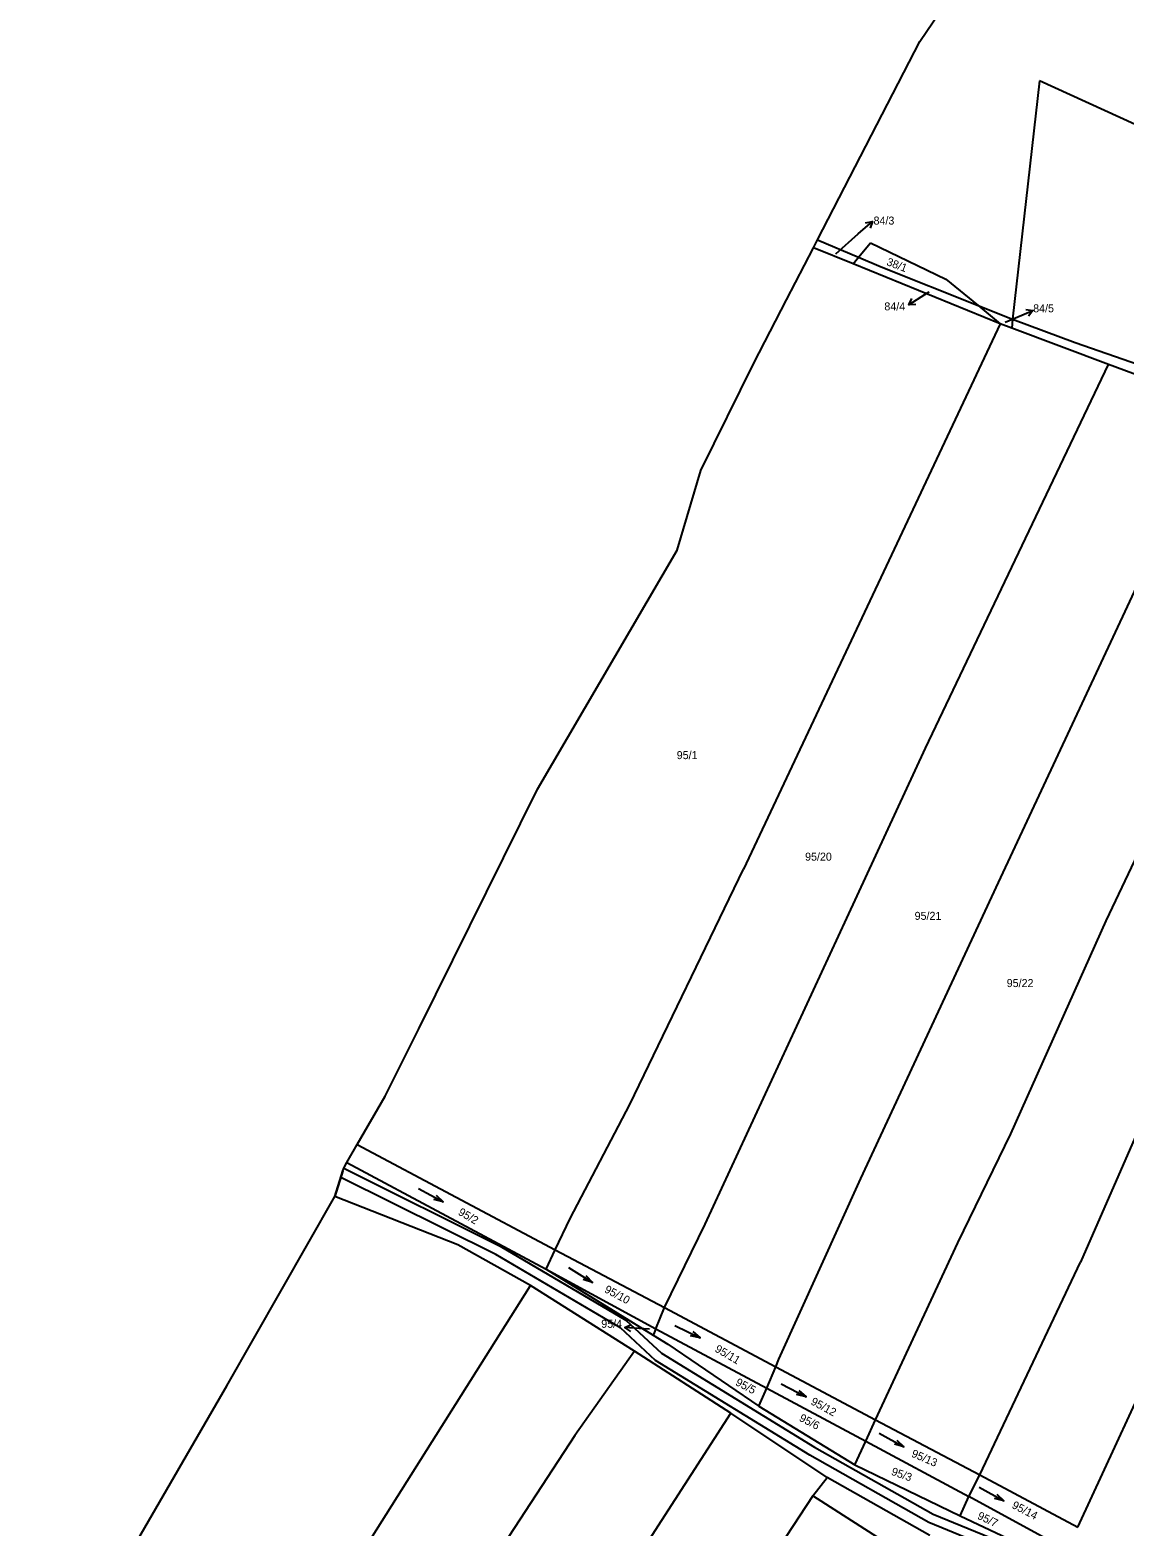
# Model space of a CAD drawing. Extents: x -747333 to -745433, y -1133152 to -1130600.
# Drawn here: x -746763 to -746530.4, y -1131462 to -1131144.2 of the extents above; entities that cross this region are included whole.
import ezdxf

# ---------------------------------------------------------------- set-up
doc = ezdxf.new("R2010")
doc.units = 0
for name, color, linetype in [('Vrstva 1', 7, 'Continuous'), ('Vrstva 13', 7, 'Continuous'), ('Vrstva 16', 7, 'Continuous'), ('Vrstva 18', 7, 'Continuous'), ('Vrstva 25', 7, 'Continuous'), ('Vrstva 30', 7, 'Continuous'), ('Vrstva 52', 7, 'Continuous'), ('Vrstva 6', 7, 'Continuous')]:
    doc.layers.add(name, color=color, linetype=linetype)

msp = doc.modelspace()

# ---------------------------------------------------------------- linework, layer by layer
at = {"layer": 'Vrstva 1'}
for points in [[(-746595.54, -1131188.72), (-746586.85, -1131192.45)], [(-746588, -1131193.84), (-746596.42, -1131190.42)], [(-746586.85, -1131192.45), (-746582.06, -1131194.51)], [(-746556.74, -1131206.56), (-746588, -1131193.84)], [(-746582.06, -1131194.51), (-746561.42, -1131202.72)], [(-746561.42, -1131202.72), (-746554.12, -1131205.63)], [(-746554.12, -1131205.63), (-746540.76, -1131210.57)], [(-746554.27, -1131207.49), (-746556.74, -1131206.56)], [(-746533.7, -1131215.25), (-746554.27, -1131207.49)], [(-746540.76, -1131210.57), (-746507.14, -1131222.24)], [(-746509.39, -1131224.25), (-746533.7, -1131215.25)], [(-746693.38, -1131380.95), (-746651.29, -1131403.28)], [(-746695.57, -1131384.74), (-746653.24, -1131407.37)], [(-746672.02, -1131402.26), (-746698.14, -1131392)], [(-746656.6, -1131410.85), (-746672.02, -1131402.26)], [(-746651.29, -1131403.28), (-746628.09, -1131415.58)], [(-746653.24, -1131407.37), (-746629.9, -1131420.11)], [(-746653.24, -1131407.37), (-746630.51, -1131421.39)], [(-746634.47, -1131424.8), (-746656.6, -1131410.85)], [(-746628.09, -1131415.58), (-746604.44, -1131428.12)], [(-746630.51, -1131421.39), (-746627.36, -1131423.33)], [(-746629.9, -1131420.11), (-746606.35, -1131432.7)], [(-746613.96, -1131437.96), (-746634.47, -1131424.8)], [(-746627.36, -1131423.33), (-746608.05, -1131436.52)], [(-746604.44, -1131428.12), (-746583.2, -1131439.38)], [(-746606.35, -1131432.7), (-746585.32, -1131443.94)], [(-746608.05, -1131436.52), (-746587.65, -1131448.97)], [(-746593.49, -1131451.66), (-746613.96, -1131437.96)], [(-746583.2, -1131439.38), (-746561.09, -1131451.11)], [(-746585.32, -1131443.94), (-746563.37, -1131455.67)], [(-746587.65, -1131448.97), (-746565.25, -1131459.83)], [(-746571.68, -1131464), (-746593.49, -1131451.66)], [(-746561.09, -1131451.11), (-746540.23, -1131462.22)], [(-746542.47, -1131467.06), (-746563.37, -1131455.67)], [(-746565.25, -1131459.83), (-746543.78, -1131469.9)]]:
    msp.add_lwpolyline(points, dxfattribs=at)
at = {"layer": 'Vrstva 13'}
for points in [[(-746573.83, -1131146.6), (-746562.93, -1131130.47)], [(-746595.54, -1131188.72), (-746573.83, -1131146.6)], [(-746596.42, -1131190.42), (-746595.54, -1131188.72)], [(-746602.14, -1131201.52), (-746596.42, -1131190.42)], [(-746609.07, -1131214.96), (-746602.14, -1131201.52)], [(-746620.38, -1131237.72), (-746609.07, -1131214.96)], [(-746625.38, -1131254.67), (-746620.38, -1131237.72)], [(-746655.09, -1131305.42), (-746625.38, -1131254.67)], [(-746680.29, -1131356.36), (-746655.09, -1131305.42)], [(-746687.43, -1131370.65), (-746680.29, -1131356.36)], [(-746693.38, -1131380.95), (-746687.43, -1131370.65)], [(-746695.57, -1131384.74), (-746693.38, -1131380.95)], [(-746696.44, -1131386.49), (-746698.14, -1131392)], [(-746696.44, -1131386.49), (-746696.27, -1131385.95)], [(-746696.27, -1131385.95), (-746695.57, -1131384.74)], [(-746721.13, -1131432.18), (-746698.14, -1131392)], [(-746762.97, -1131504.51), (-746721.13, -1131432.18)]]:
    msp.add_lwpolyline(points, dxfattribs=at)
at = {"layer": 'Vrstva 16'}
for p, q in [((-746585.374858, -1131185.149161), (-746583.90426, -1131184.849426)), ((-746574.676174, -1131202.512401), (-746576.175913, -1131202.569693)), ((-746551.281717, -1131203.574896), (-746549.793754, -1131203.771025)), ((-746635.255066, -1131420.633127), (-746636.500588, -1131419.795766))]:
    msp.add_line(p, q, dxfattribs=at)
for points in [[(-746586.9, -1131187.5), (-746583.90426, -1131184.849426), (-746584.380893, -1131186.272564)], [(-746591.68, -1131191.73), (-746586.9, -1131187.5)], [(-746572.79, -1131200.44), (-746576.175913, -1131202.569693), (-746575.474809, -1131201.242684)], [(-746571.88, -1131199.87), (-746572.79, -1131200.44)], [(-746555.7, -1131206.21), (-746553.49, -1131205.3)], [(-746553.49, -1131205.3), (-746549.793754, -1131203.771025), (-746550.708351, -1131204.960988)], [(-746632.51, -1131420.07), (-746636.500588, -1131419.795766), (-746635.152228, -1131419.136657)], [(-746631.28, -1131420.15), (-746632.51, -1131420.07)]]:
    msp.add_lwpolyline(points, dxfattribs=at)
at = {"layer": 'Vrstva 25'}
for p, q in [((-746680.399719, -1131390.263234), (-746675.100281, -1131393.076766)), ((-746648.472186, -1131407.017113), (-746643.387814, -1131410.202887)), ((-746625.883282, -1131419.33836), (-746620.516718, -1131422.02164)), ((-746603.316861, -1131431.736771), (-746598.003139, -1131434.523229)), ((-746582.42364, -1131442.235176), (-746577.17636, -1131445.144824)), ((-746561.217227, -1131453.721663), (-746555.962773, -1131456.618337))]:
    msp.add_line(p, q, dxfattribs=at)
for points in [[(-746676.632299, -1131391.697302), (-746675.100281, -1131393.076766), (-746677.101222, -1131392.580542)], [(-746644.817123, -1131408.717265), (-746643.387814, -1131410.202887), (-746645.348086, -1131409.56466)], [(-746622.081966, -1131420.68), (-746620.516718, -1131422.02164), (-746622.529179, -1131421.574427)], [(-746599.542175, -1131433.1516), (-746598.003139, -1131434.523229), (-746600.006584, -1131434.03722)], [(-746578.682983, -1131443.737668), (-746577.17636, -1131445.144824), (-746579.167924, -1131444.612215)], [(-746557.472868, -1131455.214908), (-746555.962773, -1131456.618337), (-746557.955647, -1131456.09065)]]:
    msp.add_lwpolyline(points, dxfattribs=at)
at = {"layer": 'Vrstva 30'}
for p, q in [((-746696.88, -1131387.91), (-746696.44, -1131386.49)), ((-746696.27, -1131385.95), (-746662.98, -1131402.52)), ((-746663.92, -1131404.28), (-746696.88, -1131387.91)), ((-746662.98, -1131402.52), (-746636.27, -1131418.25)), ((-746637.47, -1131419.87), (-746663.92, -1131404.28)), ((-746636.27, -1131418.25), (-746628.75, -1131425.23)), ((-746629.97, -1131426.83), (-746637.47, -1131419.87)), ((-746597.2, -1131446.94), (-746629.97, -1131426.83)), ((-746628.75, -1131425.23), (-746596.18, -1131445.22)), ((-746571.87, -1131461.22), (-746597.2, -1131446.94)), ((-746596.18, -1131445.22), (-746570.99, -1131459.42)), ((-746570.99, -1131459.42), (-746530.54, -1131475.96)), ((-746531.26, -1131477.82), (-746571.87, -1131461.22))]:
    msp.add_line(p, q, dxfattribs=at)
at = {"layer": 'Vrstva 52'}
msp.add_lwpolyline([(-746762.97, -1131504.51), (-746721.13, -1131432.18), (-746698.14, -1131392), (-746696.44, -1131386.49), (-746696.27, -1131385.95), (-746695.57, -1131384.74), (-746693.38, -1131380.95), (-746687.43, -1131370.65), (-746680.29, -1131356.36), (-746655.09, -1131305.42), (-746625.38, -1131254.67), (-746620.38, -1131237.72), (-746609.07, -1131214.96), (-746602.14, -1131201.52), (-746596.42, -1131190.42), (-746595.54, -1131188.72), (-746573.83, -1131146.6), (-746562.93, -1131130.47)], dxfattribs=at)
at = {"layer": 'Vrstva 6'}
for points in [[(-746548.35, -1131154.96), (-746554.12, -1131205.63)], [(-746422.32, -1131212.47), (-746548.35, -1131154.96)], [(-746586.85, -1131192.45), (-746584.31, -1131189.41)], [(-746584.31, -1131189.41), (-746568.26, -1131197.12)], [(-746588, -1131193.84), (-746586.85, -1131192.45)], [(-746568.26, -1131197.12), (-746561.42, -1131202.72)], [(-746561.42, -1131202.72), (-746556.74, -1131206.56)], [(-746554.12, -1131205.63), (-746554.27, -1131207.49)], [(-746556.74, -1131206.56), (-746578.71, -1131253.29)], [(-746572.57, -1131296.7), (-746533.7, -1131215.25)], [(-746534.21, -1131333.41), (-746485.62, -1131231.14)], [(-746557.1, -1131325.3), (-746520.06, -1131246.03)], [(-746578.71, -1131253.29), (-746611.32, -1131322.45)], [(-746589.35, -1131332.87), (-746572.57, -1131296.7)], [(-746635.44, -1131372.4), (-746611.32, -1131322.45)], [(-746586.35, -1131388.11), (-746557.1, -1131325.3)], [(-746619.46, -1131397.81), (-746589.35, -1131332.87)], [(-746554.47, -1131378.66), (-746534.21, -1131333.41)], [(-746521.08, -1131363.53), (-746539.63, -1131405.92)], [(-746648.14, -1131396.67), (-746635.44, -1131372.4)], [(-746565.74, -1131401.78), (-746554.47, -1131378.66)], [(-746540.23, -1131462.22), (-746501.81, -1131379.22)], [(-746603.76, -1131426.5), (-746586.35, -1131388.11)], [(-746651.29, -1131403.28), (-746648.14, -1131396.67)], [(-746628.09, -1131415.58), (-746619.46, -1131397.81)], [(-746583.2, -1131439.38), (-746565.74, -1131401.78)], [(-746653.24, -1131407.37), (-746651.29, -1131403.28)], [(-746561.09, -1131451.11), (-746539.63, -1131405.92)], [(-746693.42, -1131469.27), (-746656.6, -1131410.85)], [(-746629.9, -1131420.11), (-746628.09, -1131415.58)], [(-746629.9, -1131420.11), (-746630.51, -1131421.39)], [(-746634.47, -1131424.8), (-746647.15, -1131442.71)], [(-746606.35, -1131432.7), (-746604.44, -1131428.12)], [(-746604.44, -1131428.12), (-746603.76, -1131426.5)], [(-746608.05, -1131436.52), (-746606.35, -1131432.7)], [(-746691.43, -1131558.02), (-746613.96, -1131437.96)], [(-746585.32, -1131443.94), (-746583.2, -1131439.38)], [(-746647.15, -1131442.71), (-746707, -1131534.29)], [(-746587.65, -1131448.97), (-746585.32, -1131443.94)], [(-746596.57, -1131455.55), (-746593.49, -1131451.66)], [(-746563.37, -1131455.67), (-746561.09, -1131451.11)], [(-746596.57, -1131455.55), (-746623.57, -1131496.7)], [(-746581, -1131465.55), (-746596.57, -1131455.55)], [(-746565.25, -1131459.83), (-746563.37, -1131455.67)]]:
    msp.add_lwpolyline(points, dxfattribs=at)

# ---------------------------------------------------------------- texts
at = {"layer": 'Vrstva 16'}
for s, p in [('84/3', (-746583.65, -1131185.51)), ('84/4', (-746581.349287, -1131203.74)), ('84/5', (-746549.72, -1131204.15)), ('95/4', (-746641.531006, -1131419.86))]:
    msp.add_text(s, height=1.7, dxfattribs=at).set_placement(p)
at = {"layer": 'Vrstva 18'}
for s, height, p in [('84/3', 0.1, (-746591.68, -1131191.73)), ('84/5', 0.1, (-746555.7, -1131206.21)), ('95/1', 1.7, (-746625.48, -1131299.06)), ('95/20', 1.7, (-746598.2, -1131320.63)), ('95/21', 1.7, (-746574.92, -1131333.2)), ('95/22', 1.7, (-746555.34, -1131347.48)), ('95/4', 0.1, (-746631.28, -1131420.15))]:
    msp.add_text(s, height=height, dxfattribs=at).set_placement(p)
for s, height, rotation, p in [('38/1', 1.7, 339.40602, (-746581.03, -1131194.08)), ('84/4', 0.1, 337.55625, (-746571.88, -1131199.87)), ('95/2', 1.7, 329.499, (-746672.09, -1131395.74)), ('95/10', 1.7, 331.60869, (-746641.02, -1131412.2)), ('95/11', 1.7, 329.57172, (-746617.53, -1131424.8)), ('95/5', 1.7, 332.25309, (-746613.14, -1131431.95)), ('95/12', 1.7, 331.51968, (-746597.15, -1131436.02)), ('95/6', 1.7, 332.65017, (-746599.59, -1131439.54)), ('95/13', 1.7, 336.55374, (-746575.76, -1131447.17)), ('95/3', 1.7, 340.58007, (-746580.01, -1131451.05)), ('95/14', 1.7, 332.62218, (-746554.39, -1131458.06)), ('95/7', 1.7, 334.67355, (-746561.72, -1131460.36))]:
    msp.add_text(s, height=height, rotation=rotation, dxfattribs=at).set_placement(p)

doc.saveas('drawing.dxf')
